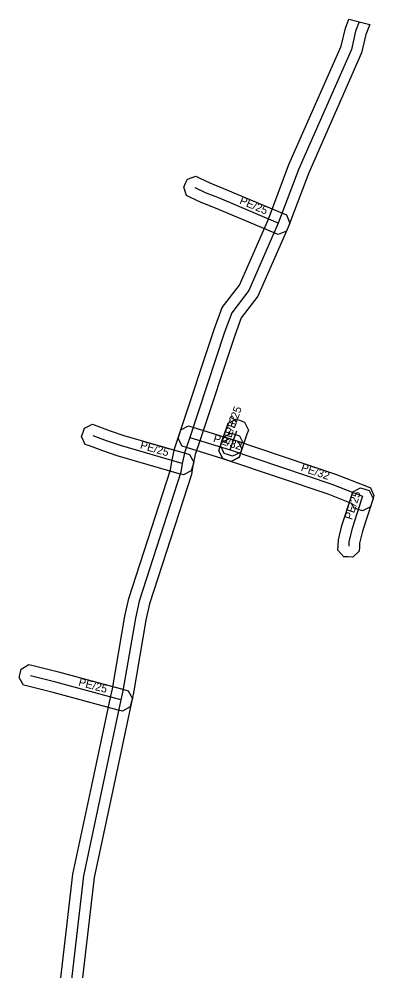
# Model space of a CAD drawing. Extents: x -681050 to -680828, y -1057939 to -1057551.
# Drawn here: x -680893.8 to -680860.5, y -1057640.5 to -1057551.3 of the extents above; entities that cross this region are included whole.
import ezdxf

# ---------------------------------------------------------------- set-up
doc = ezdxf.new("R2010")
doc.units = 0
for name, color, linetype in [('1', 7, 'Continuous'), ('24', 7, 'Continuous'), ('30', 7, 'Continuous')]:
    doc.layers.add(name, color=color, linetype=linetype)

msp = doc.modelspace()

# ---------------------------------------------------------------- linework, layer by layer
at = {"layer": '1'}
msp.add_lwpolyline([(-680890.144, -1057643.888), (-680888.698, -1057631.448), (-680886.928, -1057623.152), (-680885.178, -1057614.903), (-680885.002, -1057614.072), (-680883.832, -1057607.261), (-680883.477, -1057605.6), (-680879.557, -1057593.541), (-680879.444, -1057592.776), (-680879.174, -1057591.59), (-680878.709, -1057590.194), (-680875.434, -1057580.32), (-680874.706, -1057578.342), (-680873.097, -1057576.247), (-680870.387, -1057570.053), (-680868.466, -1057564.952), (-680863.564, -1057553.844), (-680863.178, -1057552.153), (-680862.844, -1057551.307), (-680860.899, -1057551.828), (-680861.262, -1057552.747), (-680861.656, -1057554.476), (-680866.614, -1057565.708), (-680868.533, -1057570.807), (-680871.363, -1057577.273), (-680872.934, -1057579.318), (-680873.546, -1057580.98), (-680876.811, -1057590.826), (-680877.246, -1057592.13), (-680877.476, -1057593.144), (-680877.603, -1057593.999), (-680881.543, -1057606.12), (-680881.868, -1057607.639), (-680883.038, -1057614.448), (-680883.222, -1057615.317), (-680884.972, -1057623.568), (-680886.722, -1057631.772), (-680888.156, -1057644.112)], dxfattribs=at)
for points in [[(-680869.468, -1057571.512), (-680869.849, -1057571.351), (-680875.359, -1057569.025), (-680876.693, -1057568.496), (-680877.676, -1057568.02), (-680878.049, -1057567.839), (-680878.321, -1057567.057), (-680878.14, -1057566.684), (-680877.959, -1057566.311), (-680877.177, -1057566.039), (-680876.804, -1057566.22), (-680875.887, -1057566.664), (-680874.601, -1057567.175), (-680869.071, -1057569.509), (-680868.69, -1057569.67), (-680868.378, -1057570.438), (-680868.539, -1057570.819), (-680868.7, -1057571.2)], [(-680878.341, -1057594.036), (-680878.739, -1057593.92), (-680884.553, -1057592.233), (-680885.885, -1057591.772), (-680887.153, -1057591.309), (-680887.542, -1057591.167), (-680887.891, -1057590.416), (-680887.749, -1057590.027), (-680887.607, -1057589.638), (-680886.856, -1057589.289), (-680886.467, -1057589.431), (-680885.215, -1057589.888), (-680883.947, -1057590.327), (-680878.181, -1057592), (-680877.783, -1057592.115), (-680877.384, -1057592.841), (-680877.5, -1057593.239), (-680877.615, -1057593.637)], [(-680877.859, -1057589.432), (-680877.463, -1057589.555), (-680873.663, -1057590.735), (-680873.267, -1057590.858), (-680872.882, -1057591.591), (-680873.005, -1057591.987), (-680873.128, -1057592.383), (-680873.861, -1057592.768), (-680874.257, -1057592.645), (-680878.057, -1057591.465), (-680878.453, -1057591.342), (-680878.838, -1057590.609), (-680878.715, -1057590.213), (-680878.592, -1057589.817)], [(-680874.88, -1057591.264), (-680874.743, -1057590.873), (-680874.284, -1057589.56), (-680874.147, -1057589.169), (-680873.401, -1057588.809), (-680873.01, -1057588.946), (-680872.619, -1057589.083), (-680872.259, -1057589.829), (-680872.396, -1057590.22), (-680872.855, -1057591.533), (-680872.992, -1057591.924), (-680873.738, -1057592.284), (-680874.129, -1057592.147), (-680874.52, -1057592.01)], [(-680875.039, -1057591.77), (-680874.909, -1057591.376), (-680874.748, -1057590.889), (-680874.618, -1057590.496), (-680873.879, -1057590.124), (-680873.485, -1057590.254), (-680873.092, -1057590.384), (-680872.72, -1057591.123), (-680872.85, -1057591.517), (-680873.011, -1057592.004), (-680873.141, -1057592.397), (-680873.88, -1057592.769), (-680874.274, -1057592.639), (-680874.667, -1057592.509)], [(-680862.359, -1057597.143), (-680862.587, -1057596.704), (-680864.783, -1057595.84), (-680874.28, -1057592.638), (-680874.672, -1057592.505), (-680875.04, -1057591.763), (-680874.908, -1057591.37), (-680874.775, -1057590.978), (-680874.033, -1057590.61), (-680873.64, -1057590.742), (-680864.097, -1057593.96), (-680861.204, -1057595.1), (-680860.837, -1057595.244), (-680860.498, -1057595.957), (-680860.617, -1057596.333), (-680860.708, -1057596.619), (-680860.834, -1057597.014), (-680861.569, -1057597.395), (-680861.964, -1057597.269)], [(-680860.582, -1057596.229), (-680860.709, -1057596.623), (-680861.577, -1057599.312), (-680861.845, -1057600.412), (-680861.861, -1057600.764), (-680861.879, -1057601.178), (-680862.49, -1057601.737), (-680862.904, -1057601.719), (-680863.318, -1057601.701), (-680863.877, -1057601.09), (-680863.859, -1057600.676), (-680863.835, -1057600.128), (-680863.503, -1057598.768), (-680862.613, -1057596.009), (-680862.486, -1057595.615), (-680861.748, -1057595.237), (-680861.354, -1057595.364), (-680860.96, -1057595.491)], [(-680884.061, -1057616.183), (-680884.461, -1057616.075), (-680890.551, -1057614.428), (-680892.921, -1057613.841), (-680893.323, -1057613.741), (-680893.75, -1057613.031), (-680893.651, -1057612.629), (-680893.551, -1057612.227), (-680892.841, -1057611.8), (-680892.439, -1057611.899), (-680890.049, -1057612.492), (-680883.939, -1057614.145), (-680883.539, -1057614.253), (-680883.127, -1057614.971), (-680883.235, -1057615.371), (-680883.343, -1057615.771)]]:
    msp.add_lwpolyline(points, close=True, dxfattribs=at)
at = {"layer": '24'}
for points in [[(-680861.871, -1057551.568), (-680862.22, -1057552.45), (-680862.61, -1057554.16), (-680867.54, -1057565.33), (-680869.46, -1057570.43), (-680872.23, -1057576.76), (-680873.82, -1057578.83), (-680874.49, -1057580.65), (-680877.76, -1057590.51), (-680878.21, -1057591.86), (-680878.46, -1057592.96), (-680878.58, -1057593.77), (-680882.51, -1057605.86), (-680882.85, -1057607.45), (-680884.02, -1057614.26), (-680884.2, -1057615.11), (-680885.95, -1057623.36), (-680887.71, -1057631.61), (-680889.15, -1057644)], [(-680869.46, -1057570.43), (-680874.98, -1057568.1), (-680876.29, -1057567.58), (-680877.24, -1057567.12)], [(-680878.46, -1057592.96), (-680884.25, -1057591.28), (-680885.55, -1057590.83), (-680886.81, -1057590.37)], [(-680873.799, -1057591.203), (-680873.34, -1057589.89)], [(-680877.76, -1057590.51), (-680873.96, -1057591.69)], [(-680873.96, -1057591.69), (-680873.799, -1057591.203)], [(-680873.96, -1057591.69), (-680864.44, -1057594.9), (-680861.57, -1057596.03), (-680861.661, -1057596.316)], [(-680861.661, -1057596.316), (-680862.54, -1057599.04), (-680862.84, -1057600.27), (-680862.86, -1057600.72)], [(-680884.2, -1057615.11), (-680890.3, -1057613.46), (-680892.68, -1057612.87)]]:
    msp.add_lwpolyline(points, dxfattribs=at)

# ---------------------------------------------------------------- texts
at = {"layer": '30'}
for s, rotation, p in [('PE/25', 337.11532, (-680873.155, -1057568.586)), ('PE/25', 70.73134, (-680873.769, -1057590.346)), ('PE/32', 71.70635, (-680874.079, -1057591.247)), ('PE/32', 342.74906, (-680875.612, -1057590.915)), ('PE/25', 343.81963, (-680882.46, -1057591.541)), ('PE/32', 341.36667, (-680867.396, -1057593.636)), ('PE/25', 72.11577, (-680862.564, -1057598.295)), ('PE/25', 344.86416, (-680888.233, -1057613.765))]:
    msp.add_text(s, height=0.75, rotation=rotation, dxfattribs=at).set_placement(p)

doc.saveas('drawing.dxf')
